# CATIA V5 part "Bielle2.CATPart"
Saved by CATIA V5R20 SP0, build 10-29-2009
Part number: Bielle2
Bounding box of the stored display mesh (mm): x 11.975 to 41, y 23.501 to 42.999, z -17 to -14
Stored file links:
  E:\Boulot\SeaTech\2eme ANNEE\FabricationAdditive\TP_MOSM_CREM\Projet Sauterelle de serrage\CAO Assemblage Sauterelle\Bielle2.CATPart
  E:\Boulot\SeaTech\2eme ANNEE\FabricationAdditive\TP_MOSM_CREM\Projet Sauterelle de serrage\CAO Assemblage Sauterelle\Sauterelle_horizontale_05120-06.CATPart
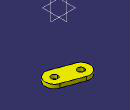
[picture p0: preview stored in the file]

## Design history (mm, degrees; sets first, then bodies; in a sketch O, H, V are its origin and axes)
Body1 (main body)
  Solid1 "05120-06_14": solid without history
